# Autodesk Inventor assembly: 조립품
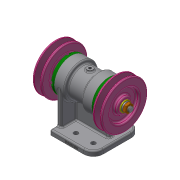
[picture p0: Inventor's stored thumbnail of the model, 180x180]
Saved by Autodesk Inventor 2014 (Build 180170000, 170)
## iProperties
Created: 2020-06
Part Number: 조립품
Document SubType Name: Assembly
Designer: kh
Author: kh
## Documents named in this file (12)
- C:\Users\kh\Desktop\700606V1033\조립품.iam
- C:\Users\kh\Desktop\700606V1033\본체.ipt
- C:\Users\kh\Desktop\700606V1033\V-벨트풀리.ipt
- C:\Users\kh\Desktop\700606V1033\너트 M10.ipt
- C:\Users\kh\Desktop\700606V1033\베어링 6204.ipt
- C:\Users\kh\Desktop\700606V1033\볼트 M4.ipt
- C:\Users\kh\Desktop\700606V1033\스프링 와셔 10.ipt
- C:\Users\kh\Desktop\700606V1033\오일 실 20 32 5.ipt
- C:\Users\kh\Desktop\700606V1033\축.ipt
- C:\Users\kh\Desktop\700606V1033\커버.ipt
- C:\Users\kh\Desktop\700606V1033\키 5x5x12.ipt
- C:\Users\kh\Desktop\700606V1033\평면 와셔 10x21.ipt
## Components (2 placed, 1 different names)
1. V-벨트풀리:1 — Mate:37, Mate:40, Mate:41
2. V-벨트풀리:2 — Mate:36, Mate:38, Mate:39
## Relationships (6: Mate 6)
- Mate:36: V-벨트풀리:2
- Mate:37: V-벨트풀리:1
- Mate:38: V-벨트풀리:2
- Mate:39: V-벨트풀리:2
- Mate:40: V-벨트풀리:1
- Mate:41: V-벨트풀리:1
